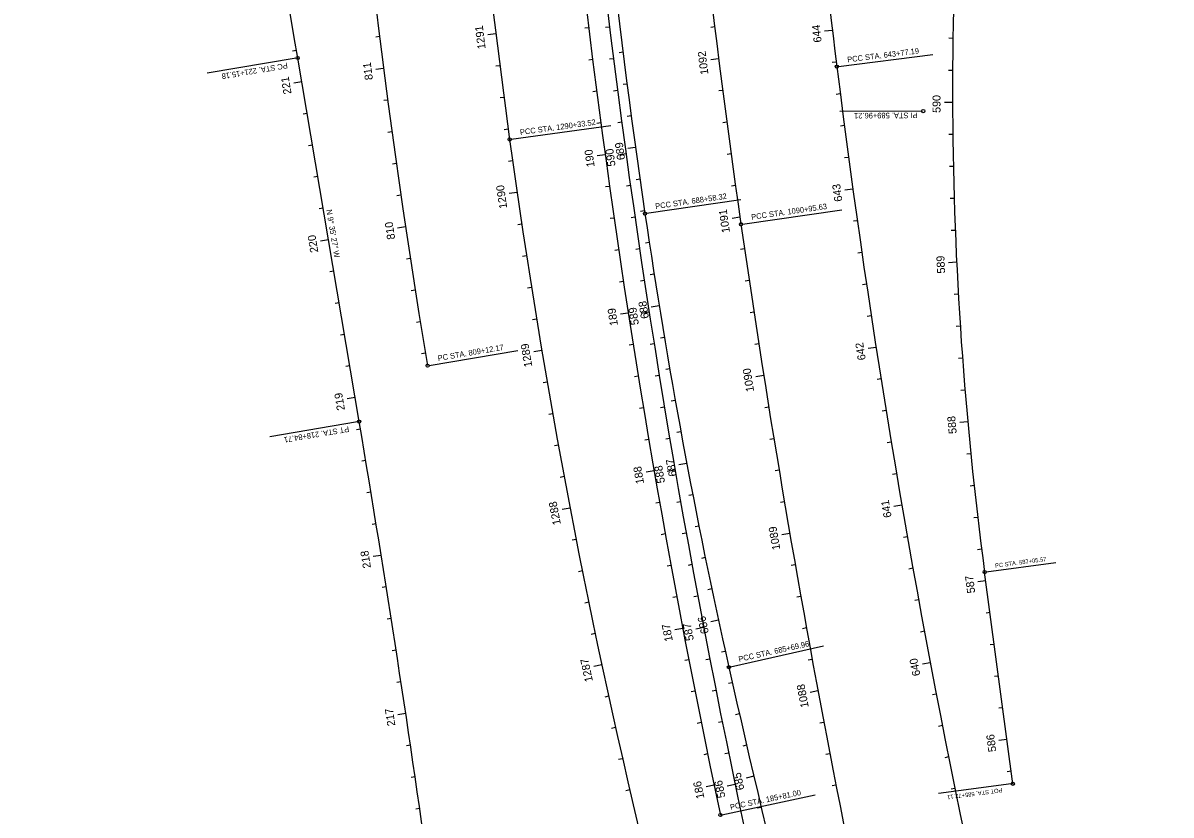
# Model space of a CAD drawing. Extents: x 919452 to 931278, y 583254 to 665650.
# Drawn here: x 928661 to 929379, y 634438 to 634933 of the extents above; entities that cross this region are included whole.
import ezdxf

# ---------------------------------------------------------------- set-up
doc = ezdxf.new("R2010")
doc.units = 0
for name, color, linetype in [('CLConst_dp', 7, 'Continuous'), ('CurveDataLabel_dp', 7, 'Continuous'), ('StationTicL_dp', 7, 'Continuous'), ('StationTicS_dp', 7, 'Continuous'), ('TextBLStation', 7, 'Continuous'), ('TextLabel', 7, 'Continuous')]:
    doc.layers.add(name, color=color, linetype=linetype)

msp = doc.modelspace()

# ---------------------------------------------------------------- linework, layer by layer
at = {"layer": 'CLConst_dp'}
for p, q in [((928871.61, 634683.73), (928833.21, 634910.97)), ((929280.08, 634457.41), (929262.46, 634589.7))]:
    msp.add_line(p, q, dxfattribs=at)
for centre, radius, start, end in [((934714.76, 635630.15), 5729.58, 175.955434, 198.89818), ((919023.27, 633253.37), 9949, 9.590734, 14.358327), ((934757.45, 635620.79), 5705.58, 180.06217, 188.19915), ((934313.46, 635582.15), 5319.04, 180.05369, 188.30596), ((932014.36, 635260.36), 2866.29, 174.76849, 187.10964), ((933567.21, 635491.59), 4644.7, 180.06217, 187.81416), ((933433.97, 635482.4), 4583.66, 182.98469, 189.59073), ((931534.4, 634892.3), 2292, 173.13281, 187.58667), ((934714.76, 635630.15), 5742.58, 186.884702, 191.983164), ((935122.08, 635647.98), 5998.08, 187.109635, 196.766064), ((933402.41, 635468.98), 4478.35, 187.81416, 199.75791), ((932825.39, 635364.91), 3815.19, 188.30596, 192.63655), ((936244.12, 635835), 7207.6, 188.199151, 193.884708), ((919061.67, 633026.13), 9949, 6.138854, 9.590734), ((936128.21, 636105.39), 7200, 192.636554, 198.491034)]:
    msp.add_arc(centre, radius, start, end, dxfattribs=at)
at = {"layer": 'CurveDataLabel_dp'}
for p, q in [((929171.1, 634905.73), (929230.2, 634913.1)), ((928832.22, 634910.8), (928776.69, 634901.42)), ((929223.09, 634877.79), (929171.89, 634877.47)), ((928966.63, 634860.23), (929028.82, 634868.77)), ((929051.21, 634813.91), (929110.21, 634822.53)), ((929111.18, 634807.23), (929173.32, 634816.19)), ((928915.36, 634718.88), (928970.77, 634728.25)), ((928870.62, 634683.56), (928815.78, 634674.29)), ((929263.45, 634589.83), (929306.96, 634595.62)), ((929103.59, 634530.49), (929161.7, 634543.52)), ((929279.09, 634457.28), (929233.64, 634451.22)), ((929098.29, 634438.06), (929156.54, 634450.42))]:
    msp.add_line(p, q, dxfattribs=at)
for centre in [(928833.21, 634910.97), (929170.11, 634905.6), (929224.09, 634877.79), (928965.64, 634860.1), (929050.22, 634813.77), (929110.19, 634807.09), (928914.38, 634718.72), (928871.61, 634683.73), (929262.46, 634589.7), (929102.62, 634530.27), (929280.08, 634457.41), (929097.32, 634437.85)]:
    msp.add_circle(centre, 1, dxfattribs=at)
at = {"layer": 'StationTicL_dp'}
for p, q in [((928957.07, 634926.02), (928952.11, 634925.41)), ((929167.38, 634928.25), (929162.41, 634927.67)), ((928886.88, 634904.51), (928881.92, 634903.88)), ((929096.25, 634910.52), (929091.29, 634909.9)), ((928835.74, 634896), (928830.81, 634895.17)), ((929242.42, 634883.24), (929237.42, 634883.22)), ((929044.36, 634855.04), (929039.41, 634854.35)), ((929025.34, 634850.54), (929020.39, 634849.86)), ((929038.4, 634851.02), (929033.45, 634850.34)), ((928970.32, 634826.9), (928965.38, 634826.19)), ((929180.16, 634829.07), (929175.21, 634828.39)), ((929109.57, 634811.42), (929104.62, 634810.71)), ((928900.57, 634805.45), (928895.63, 634804.72)), ((928852.4, 634797.4), (928847.47, 634796.57)), ((929244.99, 634783.28), (929240, 634783.05)), ((929059.09, 634756.13), (929054.15, 634755.33)), ((929039.78, 634751.59), (929034.84, 634750.82)), ((929052.86, 634752.07), (929047.92, 634751.31)), ((928985.76, 634728.11), (928980.83, 634727.28)), ((929194.64, 634730.12), (929189.7, 634729.36)), ((929124.46, 634712.53), (929119.52, 634711.75)), ((928869.06, 634698.8), (928864.13, 634697.97)), ((929251.93, 634683.53), (929246.95, 634683.08)), ((929055.94, 634652.9), (929051.01, 634652.05)), ((929069.05, 634653.39), (929064.12, 634652.54)), ((929076.33, 634657.63), (929071.42, 634656.7)), ((929210.76, 634631.43), (929205.83, 634630.59)), ((929003.41, 634629.68), (928998.5, 634628.74)), ((929140.72, 634613.86), (929135.79, 634613.02)), ((928885.37, 634600.14), (928880.43, 634599.35)), ((929263.2, 634584.18), (929258.24, 634583.52)), ((929073.82, 634554.51), (929068.9, 634553.58)), ((929086.95, 634555.01), (929082.04, 634554.07)), ((929096.16, 634559.62), (929091.27, 634558.56)), ((929023.24, 634531.67), (929018.35, 634530.62)), ((929228.53, 634533.03), (929223.62, 634532.1)), ((929158.34, 634515.43), (929153.43, 634514.51)), ((928900.69, 634501.32), (928895.75, 634500.58)), ((929276.4, 634485.05), (929271.44, 634484.39)), ((929118.25, 634462.09), (929113.38, 634460.95)), ((929093.4, 634456.45), (929088.51, 634455.43)), ((929106.58, 634456.96), (929101.68, 634455.93))]:
    msp.add_line(p, q, dxfattribs=at)
at = {"layer": 'StationTicS_dp'}
for p, q in [((929015.04, 634929.87), (929012.55, 634929.56)), ((929028.07, 634930.35), (929025.59, 634930.05)), ((929093.8, 634930.37), (929091.32, 634930.07)), ((928884.41, 634924.36), (928881.93, 634924.05)), ((929242.61, 634923.24), (929240.11, 634923.28)), ((928832.41, 634915.72), (928829.94, 634915.31)), ((929036.49, 634914.52), (929034.01, 634914.2)), ((928959.55, 634906.17), (928957.07, 634905.86)), ((929017.51, 634910.02), (929015.03, 634909.71)), ((929030.55, 634910.51), (929028.07, 634910.19)), ((929169.77, 634908.39), (929167.29, 634908.08)), ((929242.43, 634903.24), (929239.93, 634903.26)), ((929020.05, 634890.19), (929017.57, 634889.86)), ((929033.1, 634890.67), (929030.62, 634890.35)), ((929039.04, 634894.68), (929036.56, 634894.36)), ((929098.78, 634890.68), (929096.3, 634890.36)), ((928889.45, 634884.68), (928886.97, 634884.35)), ((928962.12, 634886.34), (928959.64, 634886.01)), ((929172.26, 634888.55), (929169.78, 634888.23)), ((928839.07, 634876.28), (928836.61, 634875.87)), ((929022.66, 634870.36), (929020.19, 634870.03)), ((929035.71, 634870.84), (929033.24, 634870.51)), ((929041.66, 634874.85), (929039.19, 634874.52)), ((929101.37, 634870.85), (929098.89, 634870.52)), ((929174.83, 634868.71), (929172.35, 634868.39)), ((928892.1, 634864.85), (928889.62, 634864.52)), ((928964.77, 634866.52), (928962.29, 634866.18)), ((929242.58, 634863.24), (929240.08, 634863.21)), ((928842.4, 634856.56), (928839.94, 634856.15)), ((928967.5, 634846.7), (928965.02, 634846.36)), ((929104.04, 634851.03), (929101.56, 634850.69)), ((929177.46, 634848.89), (929174.98, 634848.55)), ((928894.84, 634845.04), (928892.36, 634844.69)), ((929242.92, 634843.25), (929240.42, 634843.19)), ((928845.74, 634836.84), (928843.27, 634836.43)), ((929047.13, 634835.23), (929044.66, 634834.88)), ((928897.66, 634825.24), (928895.19, 634824.88)), ((929028.09, 634830.73), (929025.62, 634830.38)), ((929041.15, 634831.21), (929038.68, 634830.86)), ((929106.77, 634831.22), (929104.29, 634830.87)), ((929243.44, 634823.25), (929240.94, 634823.18)), ((928849.07, 634817.12), (928846.6, 634816.71)), ((929030.91, 634810.93), (929028.44, 634810.57)), ((929043.98, 634811.41), (929041.5, 634811.06)), ((929049.98, 634815.43), (929047.5, 634815.07)), ((928973.24, 634807.12), (928970.76, 634806.75)), ((929182.92, 634809.26), (929180.45, 634808.91)), ((929244.13, 634803.27), (929241.63, 634803.17)), ((929033.8, 634791.14), (929031.33, 634790.77)), ((929046.87, 634791.62), (929044.4, 634791.26)), ((929052.91, 634795.65), (929050.44, 634795.28)), ((929112.44, 634791.62), (929109.97, 634791.26)), ((929185.75, 634789.46), (929183.28, 634789.1)), ((928903.57, 634785.68), (928901.1, 634785.3)), ((928976.24, 634787.34), (928973.76, 634786.96)), ((928855.73, 634777.68), (928853.27, 634777.27)), ((929055.95, 634775.88), (929053.48, 634775.49)), ((929036.76, 634771.36), (929034.28, 634770.98)), ((929049.83, 634771.84), (929047.36, 634771.47)), ((929115.36, 634771.84), (929112.89, 634771.47)), ((929188.65, 634769.67), (929186.17, 634769.31)), ((928906.65, 634765.92), (928904.18, 634765.53)), ((928979.32, 634767.58), (928976.85, 634767.19)), ((929246.03, 634763.31), (929243.54, 634763.17)), ((928859.06, 634757.96), (928856.6, 634757.54)), ((928909.82, 634746.17), (928907.36, 634745.77)), ((928982.5, 634747.84), (928980.03, 634747.43)), ((929118.34, 634752.06), (929115.87, 634751.68)), ((929191.61, 634749.89), (929189.14, 634749.52)), ((929247.24, 634743.35), (929244.75, 634743.19)), ((928862.4, 634738.24), (928859.93, 634737.82)), ((929042.88, 634731.83), (929040.41, 634731.44)), ((929055.96, 634732.32), (929053.49, 634731.92)), ((929062.33, 634736.39), (929059.86, 634735.98)), ((929121.37, 634732.29), (929118.9, 634731.91)), ((928913.08, 634726.44), (928910.61, 634726.03)), ((928865.73, 634718.52), (928863.26, 634718.1)), ((929248.63, 634723.4), (929246.14, 634723.21)), ((929046.04, 634712.08), (929043.57, 634711.68)), ((929059.13, 634712.57), (929056.66, 634712.17)), ((929065.68, 634716.67), (929063.21, 634716.25)), ((929197.73, 634710.37), (929195.26, 634709.97)), ((928989.12, 634708.39), (928986.65, 634707.96)), ((929250.19, 634703.46), (929247.7, 634703.25)), ((929069.13, 634696.97), (929066.66, 634696.54)), ((929049.27, 634692.34), (929046.8, 634691.93)), ((929062.37, 634692.83), (929059.9, 634692.42)), ((929127.6, 634692.78), (929125.13, 634692.38)), ((929200.89, 634690.62), (929198.42, 634690.22)), ((928992.56, 634688.69), (928990.1, 634688.25)), ((928872.39, 634679.08), (928869.93, 634678.66)), ((929072.68, 634677.29), (929070.22, 634676.84)), ((928996.09, 634669), (928993.63, 634668.55)), ((929052.57, 634672.62), (929050.11, 634672.2)), ((929065.67, 634673.11), (929063.21, 634672.69)), ((929130.8, 634673.04), (929128.33, 634672.63)), ((929204.11, 634670.88), (929201.65, 634670.47)), ((929253.84, 634663.62), (929251.35, 634663.38)), ((928875.7, 634659.35), (928873.23, 634658.94)), ((929134.05, 634653.3), (929131.58, 634652.89)), ((928999.7, 634649.33), (928997.25, 634648.87)), ((929207.41, 634651.15), (929204.94, 634650.74)), ((928878.96, 634639.62), (928876.49, 634639.22)), ((929255.92, 634643.73), (929253.43, 634643.46)), ((929059.38, 634633.2), (929056.92, 634632.77)), ((929072.49, 634633.69), (929070.03, 634633.26)), ((929080.09, 634637.99), (929077.64, 634637.51)), ((929137.36, 634633.58), (929134.89, 634633.16)), ((928882.18, 634619.88), (928879.71, 634619.48)), ((929083.96, 634618.36), (929081.5, 634617.87)), ((929258.17, 634623.86), (929255.69, 634623.57)), ((929007.2, 634610.04), (929004.75, 634609.56)), ((929062.89, 634613.51), (929060.42, 634613.07)), ((929076, 634614), (929073.54, 634613.56)), ((929214.18, 634611.73), (929211.72, 634611.3)), ((929260.6, 634604.01), (929258.12, 634603.69)), ((929087.92, 634598.76), (929085.47, 634598.26)), ((929011.08, 634590.42), (929008.63, 634589.93)), ((929066.46, 634593.83), (929064, 634593.38)), ((929079.59, 634594.33), (929077.13, 634593.88)), ((929144.13, 634594.16), (929141.67, 634593.73)), ((929217.67, 634592.04), (929215.21, 634591.6)), ((928888.51, 634580.39), (928886.04, 634580)), ((929070.1, 634574.17), (929067.65, 634573.71)), ((929083.24, 634574.66), (929080.78, 634574.2)), ((929091.99, 634579.18), (929089.54, 634578.66)), ((929147.6, 634574.46), (929145.14, 634574.02)), ((929015.05, 634570.82), (929012.6, 634570.31)), ((929221.23, 634572.35), (929218.77, 634571.91)), ((928891.62, 634560.63), (928889.15, 634560.24)), ((929265.84, 634564.35), (929263.36, 634564.02)), ((929151.13, 634554.77), (929148.67, 634554.33)), ((929224.85, 634552.68), (929222.39, 634552.23)), ((929019.1, 634551.23), (929016.65, 634550.72)), ((928894.68, 634540.87), (928892.21, 634540.49)), ((929100.43, 634540.08), (929097.99, 634539.54)), ((929268.48, 634544.53), (929266, 634544.2)), ((929077.6, 634534.87), (929075.14, 634534.4)), ((929090.74, 634535.37), (929088.29, 634534.9)), ((929154.71, 634535.1), (929152.25, 634534.65)), ((929271.12, 634524.7), (929268.64, 634524.37)), ((928897.71, 634521.1), (928895.23, 634520.72)), ((929104.8, 634520.56), (929102.36, 634520.01)), ((929027.47, 634512.12), (929025.03, 634511.58)), ((929081.44, 634515.25), (929078.99, 634514.76)), ((929094.6, 634515.75), (929092.15, 634515.26)), ((929232.28, 634513.38), (929229.83, 634512.91)), ((929273.76, 634504.88), (929271.28, 634504.55)), ((929085.36, 634495.63), (929082.91, 634495.14)), ((929098.52, 634496.14), (929096.07, 634495.64)), ((929109.23, 634501.06), (929106.79, 634500.5)), ((929162.03, 634495.77), (929159.58, 634495.31)), ((929031.79, 634492.59), (929029.35, 634492.04)), ((929236.1, 634493.75), (929233.64, 634493.27)), ((928903.64, 634481.54), (928901.16, 634481.17)), ((929113.71, 634481.57), (929111.28, 634481)), ((929089.35, 634476.04), (929086.9, 634475.53)), ((929102.51, 634476.54), (929100.07, 634476.04)), ((929165.77, 634476.13), (929163.32, 634475.65)), ((929239.98, 634474.13), (929237.53, 634473.64)), ((929036.19, 634473.08), (929033.76, 634472.52)), ((928906.54, 634461.75), (928904.07, 634461.39)), ((929279.04, 634465.23), (929276.56, 634464.9)), ((929040.69, 634453.59), (929038.25, 634453.02)), ((929169.57, 634456.49), (929167.12, 634456.01)), ((929243.93, 634454.52), (929241.48, 634454.03)), ((928909.41, 634441.96), (928906.93, 634441.6)), ((929122.84, 634442.62), (929120.41, 634442.05))]:
    msp.add_line(p, q, dxfattribs=at)

# ---------------------------------------------------------------- texts
at = {"layer": 'CurveDataLabel_dp'}
for s, height, rotation, p in [('PCC STA. 643+77.19', 3.5, 7.10964, (929176.84, 634908.21)), ('PC STA. 221+15.18', 3.5, 189.59073, (928826.6, 634908.08)), ('PI STA. 589+96.21', 3.5, 180.35974, (929220.6, 634876.9)), ('PCC STA. 1290+33.52', 3.5, 7.81416, (928972.34, 634862.78)), ('PCC STA. 688+58.32', 3.5, 8.30596, (929056.89, 634816.51)), ('PCC STA. 1090+95.63', 3.5, 8.19915, (929116.87, 634809.82)), ('PC STA. 809+12.17', 3.5, 9.59073, (928920.99, 634721.61)), ('PT STA. 218+84.71', 3.5, 189.59073, (928865, 634680.83)), ('PC STA. 587+05.57', 2.625, 7.58667, (929269.17, 634592.36)), ('PCC STA. 685+69.96', 3.5, 12.63655, (929109.06, 634533.51)), ('PCC STA. 185+81.00', 3.5, 11.98316, (929103.8, 634441.02)), ('POT STA. 585+72.11', 2.625, 187.58667, (929273.38, 634454.75))]:
    msp.add_text(s, height=height, rotation=rotation, dxfattribs=at).set_placement(p)
at = {"layer": 'TextBLStation'}
for s, rotation, p in [('1291', 96.99412, (928950.65, 634916.79)), ('644', 96.65372, (929160.68, 634920.94)), ('1092', 97.15108, (929089.91, 634900.83)), ('811', 97.24286, (928880.22, 634897.48)), ('221', 99.59073, (928829.37, 634888.71)), ('590', 90.22638, (929234.94, 634876.69)), ('590', 97.81552, (929031.86, 634843.54)), ('689', 97.85698, (929037.82, 634847.54)), ('190', 97.8026, (929018.8, 634843.06)), ('1290', 98.24305, (928964.16, 634817.15)), ('643', 97.847, (929173.63, 634821.52)), ('1091', 98.15528, (929103.34, 634802.06)), ('810', 98.49286, (928894.12, 634797.9)), ('220', 99.59073, (928846.09, 634789.72)), ('589', 92.7262, (929237.81, 634776.4)), ('189', 98.80034, (929033.37, 634743.98)), ('589', 98.81552, (929046.45, 634744.47)), ('688', 99.18179, (929052.73, 634748.44)), ('1289', 99.52244, (928979.82, 634718.21)), ('642', 98.80224, (929188.23, 634722.47)), ('1090', 98.95936, (929118.42, 634702.7)), ('219', 99.59073, (928862.75, 634691.11)), ('588', 95.22601, (929245.06, 634676.31)), ('188', 99.79807, (929049.67, 634645.15)), ('588', 99.81552, (929062.78, 634645.64)), ('687', 100.68357, (929070.16, 634649.88)), ('1288', 100.80184, (928997.69, 634619.61)), ('641', 99.75747, (929204.41, 634624.12)), ('1089', 99.7543, (929134.81, 634603.94)), ('218', 99.10288, (928879, 634592.46)), ('587', 97.58667, (929256.62, 634576.77)), ('686', 102.18535, (929090.21, 634551.65)), ('187', 100.79581, (929067.66, 634546.75)), ('587', 100.81552, (929080.8, 634547.25)), ('1287', 102.08123, (929017.73, 634521.57)), ('640', 100.71271, (929222.37, 634525.22)), ('1088', 100.54923, (929152.58, 634505.39)), ('217', 98.52698, (928894.23, 634493.81)), ('586', 97.58667, (929269.83, 634477.59)), ('586', 101.81552, (929100.57, 634449.03)), ('685', 103.19324, (929112.45, 634453.99)), ('186', 101.79355, (929087.39, 634448.52))]:
    msp.add_text(s, height=5, rotation=rotation, dxfattribs=at).set_placement(p)
at = {"layer": 'TextLabel'}
msp.add_text('N 9%%d 35\' 27" W', height=3.5, rotation=279.59073, dxfattribs=at).set_placement((928851.03, 634816))

doc.saveas('drawing.dxf')
